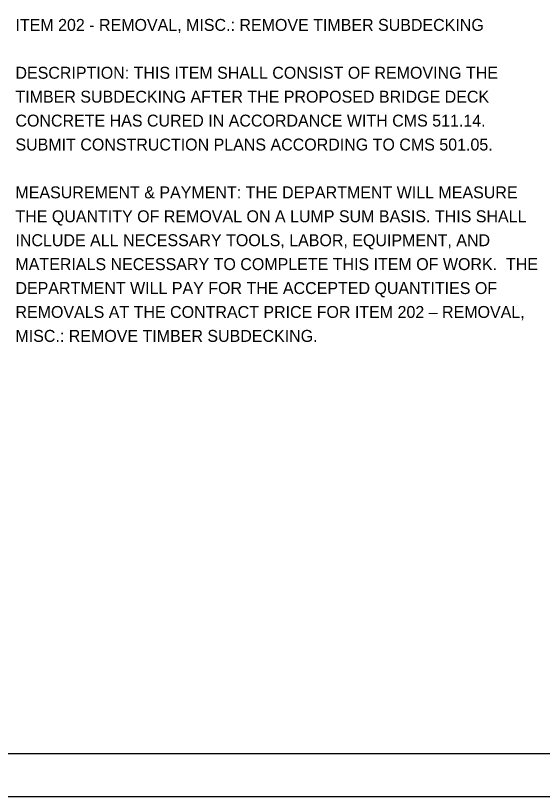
# Model space of a CAD drawing. Extents: x 0 to 34, y 0 to 22.
# Drawn here: x 24.66 to 30.83, y 0 to 9.14 of the extents above; entities that cross this region are included whole.
import ezdxf

# ---------------------------------------------------------------- set-up
doc = ezdxf.new("R2010")
doc.units = 0
for name, color, linetype in [('BR_P_Gen_Text', 7, 'Continuous'), ('SH_Border', 7, 'Continuous'), ('SH_Cut_Line', 7, 'Continuous')]:
    doc.layers.add(name, color=color, linetype=linetype)

msp = doc.modelspace()

# ---------------------------------------------------------------- linework, layer by layer
at = {"layer": 'SH_Border'}
msp.add_lwpolyline([(1.5, 21.5), (33.5, 21.5), (33.5, 0.5), (1.5, 0.5)], close=True, dxfattribs=at)
at = {"layer": 'SH_Cut_Line'}
msp.add_lwpolyline([(0, 0), (34, 0), (34, 22), (0, 22)], close=True, dxfattribs=at)

# ---------------------------------------------------------------- texts
at = {"layer": 'BR_P_Gen_Text'}
for s, p in [('ITEM 202 - REMOVAL, MISC.: REMOVE TIMBER SUBDECKING ', (24.66, 8.96)), ('DESCRIPTION: THIS ITEM SHALL CONSIST OF REMOVING THE ', (24.66, 8.4)), ('TIMBER SUBDECKING AFTER THE PROPOSED BRIDGE DECK ', (24.66, 8.12)), ('CONCRETE HAS CURED IN ACCORDANCE WITH CMS 511.14.  ', (24.66, 7.84)), ('SUBMIT CONSTRUCTION PLANS ACCORDING TO CMS 501.05.', (24.66, 7.56)), ('MEASUREMENT & PAYMENT: THE DEPARTMENT WILL MEASURE ', (24.66, 7)), ('THE QUANTITY OF REMOVAL ON A LUMP SUM BASIS. THIS SHALL ', (24.66, 6.72)), ('INCLUDE ALL NECESSARY TOOLS, LABOR, EQUIPMENT, AND ', (24.66, 6.44)), ('MATERIALS NECESSARY TO COMPLETE THIS ITEM OF WORK.  THE ', (24.66, 6.16)), ('DEPARTMENT WILL PAY FOR THE ACCEPTED QUANTITIES OF ', (24.66, 5.88)), ('REMOVALS AT THE CONTRACT PRICE FOR ITEM 202 – REMOVAL, ', (24.66, 5.6)), ('MISC.: REMOVE TIMBER SUBDECKING.', (24.66, 5.32))]:
    msp.add_text(s, height=0.14, dxfattribs=at).set_placement(p)

doc.saveas('drawing.dxf')
